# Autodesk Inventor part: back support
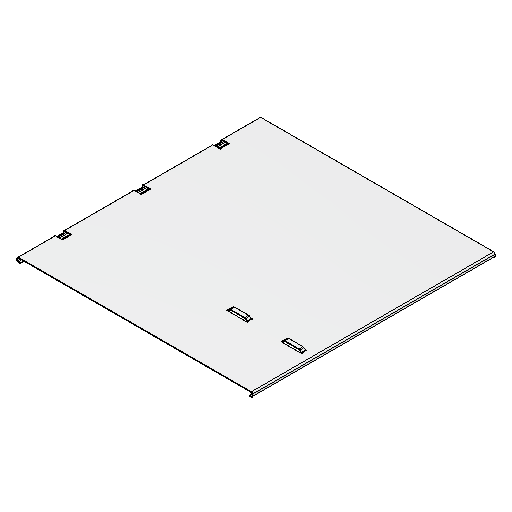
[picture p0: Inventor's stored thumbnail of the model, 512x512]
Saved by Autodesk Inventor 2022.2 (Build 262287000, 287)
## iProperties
Created: 2022-01
Part Number: back support
Material: アルミニウム 6061
Document SubType Name: Sheet Metal
Designer: taeku
Density: 2.7 g/cm^3
Sheet Metal Rule: Default_mm
Appearance: アルミニウム - フラット
Author: taeku
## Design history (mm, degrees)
node "コンター フランジ1"
  sketch "スケッチ1"
    geometry: L1 (5, 0)-(0, 0); L2 (0, 0)-(0, 7); L3 (0, 7)-(356, 7); L4 (356, 7)-(356, 0); L5 (356, 0)-(351, 0)
    constraints: 10 end point, 3 perpendicular, 2 point on line, 1 horizontal
    dimensions: "d11" = 356 distance of L2.end L3.end; "d12" = 7 distance between parallel lines of L1 L3; "d13" = 5 distance of L1.start L1.end; "d16" = 5 distance of L4.end L5.end (= d13)
sketch "スケッチ2"
  geometry: L1 (339, -270)-(309, -270); L2 (309, -270)-(309, -278); L3 (309, -278)-(339, -278); L4 (339, -278)-(339, -270); L5 (257, -270)-(227, -270); L6 (227, -270)-(227, -278); L7 (227, -278)-(257, -278); L8 (257, -278)-(257, -270); L9 (354, 0)-(354, -366) reference; L10 (352, -366)-(0, -366) reference; 1 further point
  constraints: 16 end point, 4 parallel, 2 horizontal, 2 perpendicular, 2 point on line, 1 collinear
  dimensions: "d17" = 15 distance between parallel lines of L9 L4; "d18" = 30 distance between parallel lines of L2 L4; "d19" = 82 distance between parallel lines of L6 L2; "d20" = 8 distance between parallel lines of L3 L1; "d21" = 88 distance between parallel lines of L10 L3
feature "切り取り1" sketch "スケッチ2" dims "d14" = 1 (= Thickness), "d15" = 0
node "作業平面1"
node "面1"
  sketch "スケッチ3"
    geometry: L1 (313, -271)-(335, -271); L2 (335, -271)-(335, -277); L3 (335, -277)-(313, -277); L4 (313, -277)-(313, -271); L5 (309, -270)-(339, -270) reference; L6 (339, -278)-(309, -278) reference; L7 (339, -270)-(339, -278) reference; L8 (309, -278)-(309, -270) reference; L9 (231, -271)-(253, -271); L10 (253, -271)-(253, -277); L11 (253, -277)-(231, -277); L12 (231, -277)-(231, -271); L13 (257, -270)-(257, -278) reference; L14 (227, -278)-(227, -270) reference; L15 (227, -270)-(257, -270) reference; L16 (257, -278)-(227, -278) reference; 1 further point
    constraints: 16 end point, 4 parallel, 2 horizontal, 2 perpendicular
    dimensions: "d23" = 1 distance between parallel lines of L1 L5; "d24" = 1 distance between parallel lines of L6 L3 (= d23); "d25" = 4 distance between parallel lines of L7 L2; "d26" = 4 distance between parallel lines of L8 L4 (= d25); "d27" = 4 distance between parallel lines of L10 L13 (= d25); "d28" = 4 distance between parallel lines of L14 L12 (= d25); "d29" = 1 distance between parallel lines of L9 L15 (= d23); "d30" = 1 distance between parallel lines of L16 L11 (= d23)
feature "曲げ3" dims "d0" = 1 (= Thickness), "d36" = 1 (= BendReliefWidth), "d37" = 0.5 (= BendReliefDepth), "d38" = 2 (= MinimumRemnant), "d39" = 1 (= TransitionRadius), "d40" = 1 (= BendRadius), "SeamGap" = 0.01
feature "曲げ4" dims "d0" = 1 (= Thickness), "d41" = 1 (= BendReliefWidth), "d42" = 0.5 (= BendReliefDepth), "d43" = 2 (= MinimumRemnant), "d44" = 1 (= TransitionRadius), "d45" = 1 (= BendRadius), "SeamGap" = 0.01
feature "曲げ5" dims "d0" = 1 (= Thickness), "d46" = 1 (= BendReliefWidth), "d47" = 0.5 (= BendReliefDepth), "d48" = 2 (= MinimumRemnant), "d49" = 1 (= TransitionRadius), "d50" = 1 (= BendRadius), "SeamGap" = 0.01
feature "曲げ6" dims "d0" = 1 (= Thickness), "d51" = 1 (= BendReliefWidth), "d52" = 0.5 (= BendReliefDepth), "d53" = 2 (= MinimumRemnant), "d54" = 1 (= TransitionRadius), "d55" = 1 (= BendRadius), "SeamGap" = 0.01
sketch "スケッチ4" dims "d65" = 10
  geometry: L1 (58, -2)-(72, -2); L2 (72, -2)-(72, 13); L3 (72, 13)-(58, 13); L4 (58, 13)-(58, -2); L5 (0, -3)-(366, -3) reference; L6 (0, -3)-(0, 0) reference; L7 (177, -2)-(191, -2); L8 (191, -2)-(191, 13); L9 (191, 13)-(177, 13); L10 (177, 13)-(177, -2); L11 (296, -2)-(310, -2); L12 (310, -2)-(310, 13); L13 (310, 13)-(296, 13); L14 (296, 13)-(296, -2); 1 further point
  constraints: 24 end point, 2 horizontal, 2 parallel, 1 perpendicular, 16 other
  dimensions: "d56" = 14 distance between parallel lines of L2 L4; "d57" = 15 distance between parallel lines of L1 L3; "d58" = 1 distance between parallel lines of L5 L1; "d59" = 58 distance between parallel lines of L4 L6; "d62" = 119 distance of L1.start L7.start
feature "切り取り2" sketch "スケッチ4" dims "d67" = 1 (= Thickness), "d68" = 0
node "ソリッド1"
feature "プレート1" dims "d0" = 1 (= Thickness), "d1" = 1 (= BendReliefWidth), "d2" = 0.5 (= BendReliefDepth), "d3" = 2 (= MinimumRemnant), "d4" = 1 (= TransitionRadius), "d5" = 366, "d6" = 1 (= BendRadius), "d7" = 0.5, "d8" = 4 (= CornerReliefSize), "d9" = 1 (= GapSize), "d10" = 1 (= JacobiRadiusSize), "SeamGap" = 0.01
feature "曲げ1" dims "d0" = 1 (= Thickness), "d1" = 1 (= BendReliefWidth), "d2" = 0.5 (= BendReliefDepth), "d3" = 2 (= MinimumRemnant), "d4" = 1 (= TransitionRadius), "d6" = 1 (= BendRadius), "d7" = 0.5, "SeamGap" = 0.01
feature "コーナー1" dims "d7" = 0.5, "d8" = 4 (= CornerReliefSize), "d9" = 1 (= GapSize), "d10" = 1 (= JacobiRadiusSize)
feature "プレート2" dims "d0" = 1 (= Thickness), "d31" = 1 (= BendRadius), "d32" = 1 (= BendReliefWidth), "d34" = 2 (= MinimumRemnant)
feature "曲げ2" dims "d0" = 1 (= Thickness), "d31" = 1 (= BendRadius), "d32" = 1 (= BendReliefWidth), "d33" = 0.5 (= BendReliefDepth), "d34" = 2 (= MinimumRemnant), "d35" = 1 (= TransitionRadius), "SeamGap" = 0.01
other parameters: "Thickness" = 1 (derived), "BendRadius" = 1 (= Thickness), "BendReliefWidth" = 1 (= Thickness), "BendReliefDepth" = 0.5 (= 0.5 x Thickness), "CornerReliefSize" = 4 (= 4 x Thickness), "MinimumRemnant" = 2 (= 2 x Thickness), "TransitionRadius" = 1 (= BendRadius), "JacobiRadiusSize" = 1 (= BendRadius), "GapSize" = 1 (= Thickness), "d22" = 2
